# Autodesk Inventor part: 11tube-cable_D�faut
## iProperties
Created: 2011-01
Part Number: 11tube-cable_D�faut
Document SubType Name: Modeling
Designer: eric
Density: 1 g/cm^3
Mass: 0.282743 g
Surface Area: 6.22035 cm^2
Volume: 0.282743 cm^3
Author: eric
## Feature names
1. Base1
